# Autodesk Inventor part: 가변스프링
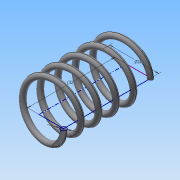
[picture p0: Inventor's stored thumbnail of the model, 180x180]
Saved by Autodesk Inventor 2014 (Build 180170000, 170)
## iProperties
Created: 2017-12
Part Number: 가변스프링
Material: 일반
Document SubType Name: Modeling
Designer: 학생용
Density: 1 g/cm^3
Appearance: 기본값
Mass: 0.871858 g
Surface Area: 17.7256 cm^2
Volume: 0.871858 cm^3
Author: 학생용
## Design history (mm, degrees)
sketch "스케치1"
  geometry: L1 (0, 0)-(9, 0); L2 (9, 0)-(9, -22.583); L3 (9, -22.583)-(0, -22.583); L4 (0, -22.583)-(0, 0); C1 r 1 at (9, 0)
  constraints: 8 end point, 2 parallel, 1 centre point, 1 coincident, 1 horizontal, 1 perpendicular
  dimensions: "d0" = 22.58289 distance of L3.end L1.start (derived); "d1" = 18 diameter of L2 L4; "d2" = 2 diameter of C1
feature "코일1" sketch "스케치1" pitch "d3" = 10; turns "d5" = 5; dims "d4" = 22.58289 (= d0), "d6" = 0, angle "d7" = 90 deg, angle "d8" = 90 deg, "d9" = 0, "d10" = 0
node "작업 평면1"
sketch "스케치2"
  geometry: L1 (8, 0)-(10, 0) reference; 1 further point
  constraints: 1 horizontal alignment
extrude "돌출1" cut sketch "스케치2" distance "d11" = 10; taper "d12" = 0 deg
node "작업 평면2"
sketch "스케치3"
  geometry: L1 (-8, 0)-(-10, 0) reference; 1 further point
  constraints: 1 horizontal alignment
extrude "돌출2" cut sketch "스케치3" distance "d13" = 10; taper "d14" = 0 deg
node "솔리드1"
node "절단 모서리 투영1"
node "절단 모서리 투영2"
